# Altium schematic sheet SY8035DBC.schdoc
size 127 x 101 mm
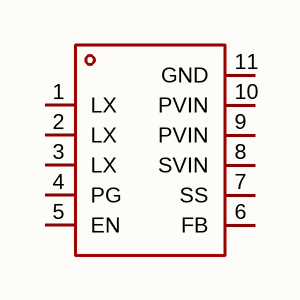
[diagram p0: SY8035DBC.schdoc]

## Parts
U?  sy8035dbc  [TDFN-10_L3.0-W3.0-P0.50-BL-EP]  (value not drawn)

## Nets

Not connected (* = marked no-connect by the designer): U? 1(LX) 2(LX) 3(LX) 4(PG) 5(EN) 6(FB) 7(SS) 8(SVIN) 9(PVIN) 10(PVIN) 11(GND)

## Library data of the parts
U? = sy8035dbc: 功能类型:降压型;工作电压:2.7V~5.5V;输出电压:600mV~5.5V;输出电流:5A;输出类型:可调;; Manufacturer: Silergy(矽力杰); AddInBom: yes; ModelId: f2c5a86f900941fe8fc94a62166302e6; ModelName: TDFN-10_L3.0-W3.0-H0.8-P0.50; ModelTransform: 118.11,118.8974,0,0,0,0,0,-0.0005,0; Function: 降压型; Output Current: 5A; Frequency - Switching: 1MHz; Synchronous Rectifier: 是; Number of Outputs: 1; Topology: 降压式; Quiescent Current: 150uA; Switch tube (built-in/external): 内置; Output Type: 可调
